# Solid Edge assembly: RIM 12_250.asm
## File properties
Title: Zylinder
Author: ahadarics
Template: iso metric assembly.asm
Last saved by: psaghy
Revision: 28
Application: Solid Edge
Username: ahadarics
Dokumentum tartalom típus: 1
Document Number: RIM 12/250
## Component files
Profilrohr.par
Kolbenstange.par
Kit_1.par
Kit_2.par
Mutter_1.par
Mutter_2.par
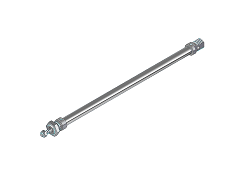
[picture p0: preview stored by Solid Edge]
